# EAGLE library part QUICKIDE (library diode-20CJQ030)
Quick Logic's QuickIDE Intel XScale PXA2xx to IDE Bridge Description: The QuickIDE device is a full featured IDE Controller companion device for the Intel XScale PXA2xxx line of embedded processors. This device offers extremely high throughput while consuming very little power. With its on-board Sector Buffer RAM, the device allows the XScale CPU to perform read and write operations in full 512- byte sectors without interruption or waiting for the externally connected IDE device to be 'ready'. This device connects to the XScale CPU via its static memory interface. Variable Latency Input and Output (VLIO) is handled automatically by the QuickIDE device through use of the RDY signal. The RDY signal is only used to properly synchronize the QuickIDE device's responses to the XScale read and write commands during high-speed bus operation the QuickIDE device does not assert the RDY signal while it is waiting for responses from the externally connected IDE device. Instead, after an IDE command is given to the QuickIDE device, an interrupt is asserted to the XScale CPU to indicate that the externally connected device has responded and that the internal sector buffer is ready for read or write. Although the IDE interface is 16-bits wide, the QuickIDE device 'stacks' the IDE data words properly in the internal sector buffers so that the XScale device can perform all read and write operations in 32-bit mode. The QuickIDE device is based upon QuickLogic's proven programmable logic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
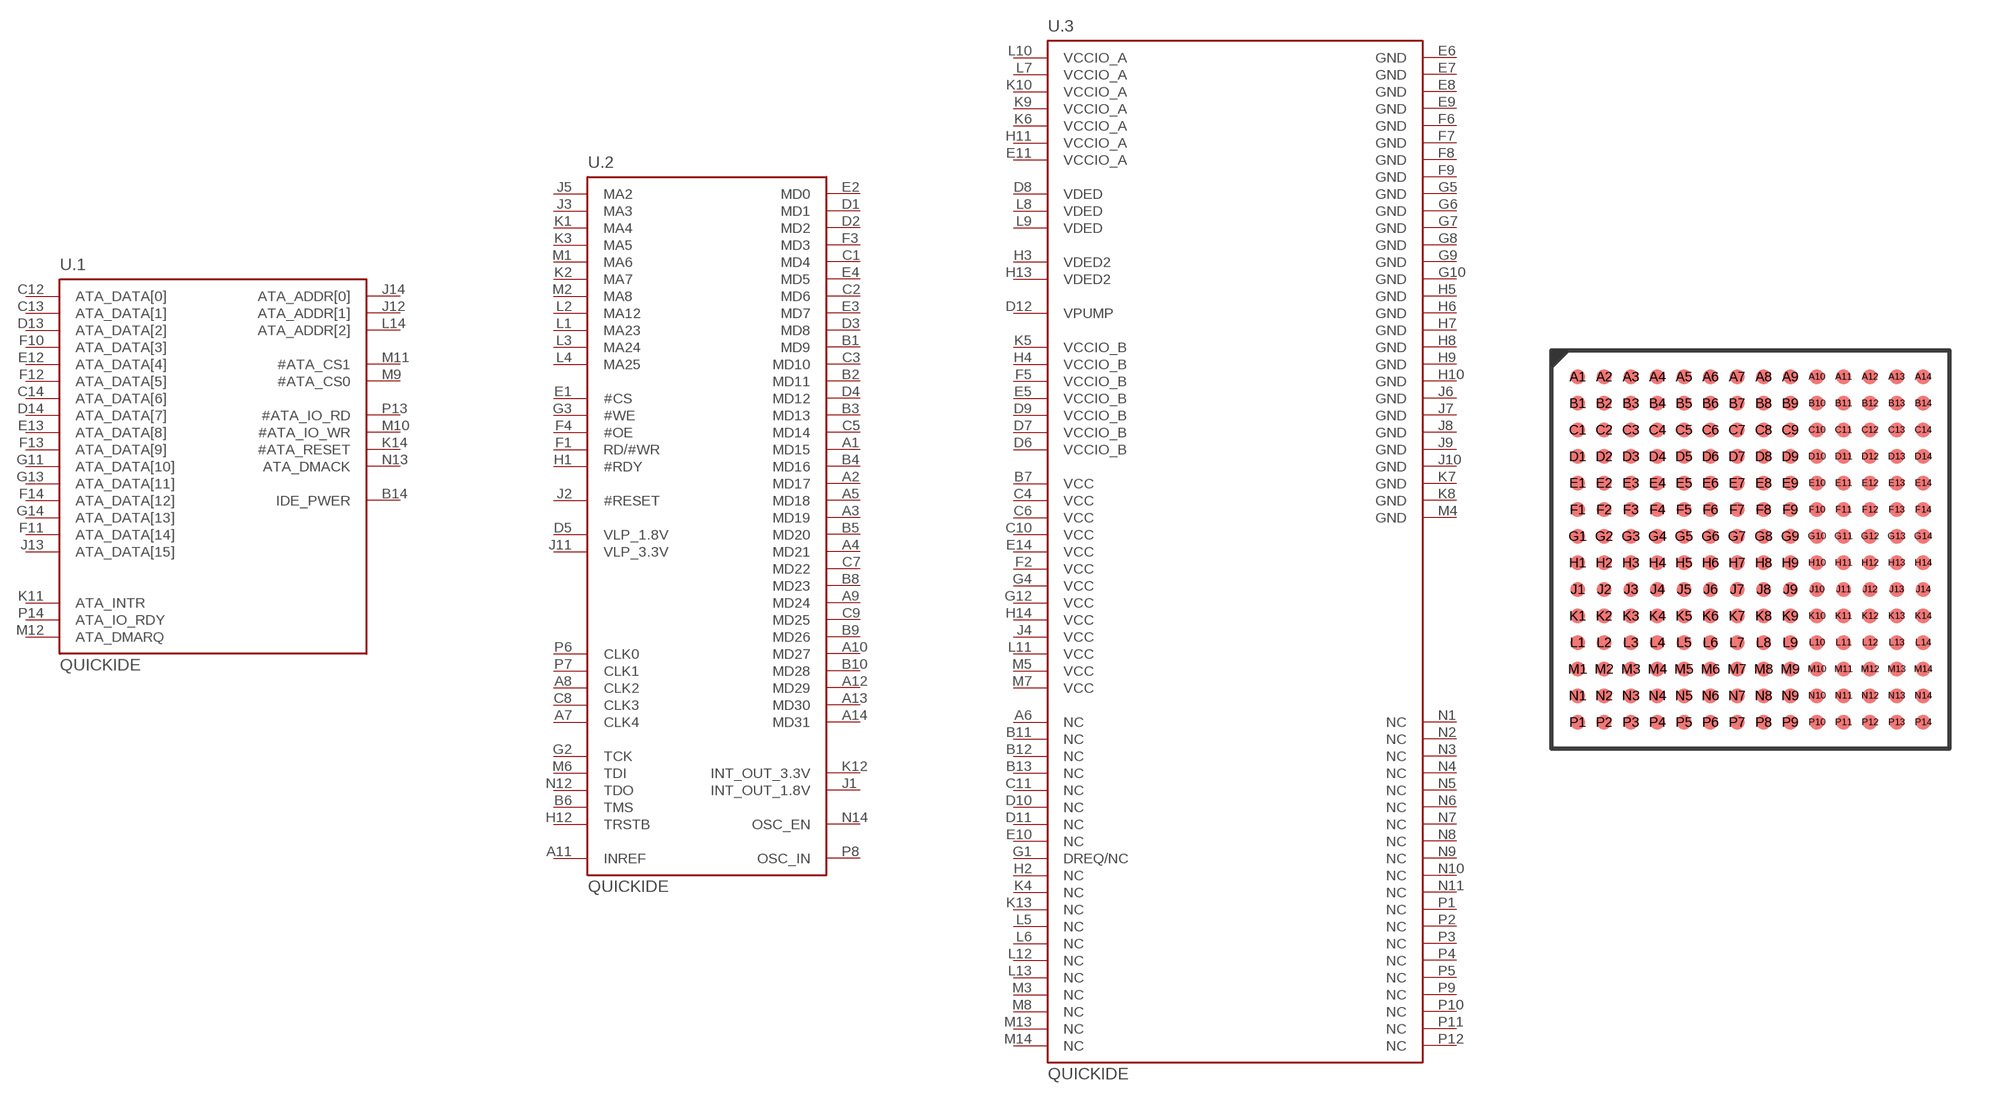
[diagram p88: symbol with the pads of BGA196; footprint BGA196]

Designator prefix U; gates .3=QUICKIDE_PWR .1=QUICKIDE_ATA .2=QUICKIDE_VLIO

## QUICKIDE-V3  [BGA196]
A1  .2:MD15
A2  .2:MD17
A3  .2:MD19
A4  .2:MD21
A5  .2:MD18
A6  .3:NC  nc
A7  .2:CLK4  in
A8  .2:CLK2  in
A9  .2:MD24
A10  .2:MD27
A11  .2:INREF  in
A12  .2:MD29
A13  .2:MD30
A14  .2:MD31
B1  .2:MD9
B2  .2:MD11
B3  .2:MD13
B4  .2:MD16
B5  .2:MD20
B6  .2:TMS  in
B7  .3:VCC  pwr
B8  .2:MD23
B9  .2:MD26
B10  .2:MD28
B11  .3:NC  nc
B12  .3:NC  nc
B13  .3:NC  nc
B14  .1:IDE_PWER  out
C1  .2:MD4
C2  .2:MD6
C3  .2:MD10
C4  .3:VCC  pwr
C5  .2:MD14
C6  .3:VCC  pwr
C7  .2:MD22
C8  .2:CLK3  in
C9  .2:MD25
C10  .3:VCC  pwr
C11  .3:NC  nc
C12  .1:ATA_DATA[0]
C13  .1:ATA_DATA[1]
C14  .1:ATA_DATA[6]
D1  .2:MD1
D2  .2:MD2
D3  .2:MD8
D4  .2:MD12
D5  .2:VLP_1.8V  in
D6  .3:VCCIO_B  pwr
D7  .3:VCCIO_B  pwr
D8  .3:VDED  pwr
D9  .3:VCCIO_B  pwr
D10  .3:NC  nc
D11  .3:NC  nc
D12  .3:VPUMP  pwr
D13  .1:ATA_DATA[2]
D14  .1:ATA_DATA[7]
E1  .2:#CS  in
E2  .2:MD0
E3  .2:MD7
E4  .2:MD5
E5  .3:VCCIO_B  pwr
E6  .3:GND  pwr
E7  .3:GND  pwr
E8  .3:GND  pwr
E9  .3:GND  pwr
E10  .3:NC  nc
E11  .3:VCCIO_A  pwr
E12  .1:ATA_DATA[4]
E13  .1:ATA_DATA[8]
E14  .3:VCC  pwr
F1  .2:RD/#WR  in
F2  .3:VCC  pwr
F3  .2:MD3
F4  .2:#OE  in
F5  .3:VCCIO_B  pwr
F6  .3:GND  pwr
F7  .3:GND  pwr
F8  .3:GND  pwr
F9  .3:GND  pwr
F10  .1:ATA_DATA[3]
F11  .1:ATA_DATA[14]
F12  .1:ATA_DATA[5]
F13  .1:ATA_DATA[9]
F14  .1:ATA_DATA[12]
G1  .3:DREQ/NC  out
G2  .2:TCK  in
G3  .2:#WE  in
G4  .3:VCC  pwr
G5  .3:GND  pwr
G6  .3:GND  pwr
G7  .3:GND  pwr
G8  .3:GND  pwr
G9  .3:GND  pwr
G10  .3:GND  pwr
G11  .1:ATA_DATA[10]
G12  .3:VCC  pwr
G13  .1:ATA_DATA[11]
G14  .1:ATA_DATA[13]
H1  .2:#RDY  out
H2  .3:NC  nc
H3  .3:VDED2  pwr
H4  .3:VCCIO_B  pwr
H5  .3:GND  pwr
H6  .3:GND  pwr
H7  .3:GND  pwr
H8  .3:GND  pwr
H9  .3:GND  pwr
H10  .3:GND  pwr
H11  .3:VCCIO_A  pwr
H12  .2:TRSTB  in
H13  .3:VDED2  pwr
H14  .3:VCC  pwr
J1  .2:INT_OUT_1.8V  out
J2  .2:#RESET  in
J3  .2:MA3  in
J4  .3:VCC  pwr
J5  .2:MA2  in
J6  .3:GND  pwr
J7  .3:GND  pwr
J8  .3:GND  pwr
J9  .3:GND  pwr
J10  .3:GND  pwr
J11  .2:VLP_3.3V
J12  .1:ATA_ADDR[1]  out
J13  .1:ATA_DATA[15]
J14  .1:ATA_ADDR[0]  out
K1  .2:MA4  in
K2  .2:MA7  in
K3  .2:MA5  in
K4  .3:NC  nc
K5  .3:VCCIO_B  pwr
K6  .3:VCCIO_A  pwr
K7  .3:GND  pwr
K8  .3:GND  pwr
K9  .3:VCCIO_A  pwr
K10  .3:VCCIO_A  pwr
K11  .1:ATA_INTR  in
K12  .2:INT_OUT_3.3V  out
K13  .3:NC  nc
K14  .1:#ATA_RESET  out
L1  .2:MA23  in
L2  .2:MA12  in
L3  .2:MA24  in
L4  .2:MA25  in
L5  .3:NC  nc
L6  .3:NC  nc
L7  .3:VCCIO_A  pwr
L8  .3:VDED  pwr
L9  .3:VDED  pwr
L10  .3:VCCIO_A  pwr
L11  .3:VCC  pwr
L12  .3:NC  nc
L13  .3:NC  nc
L14  .1:ATA_ADDR[2]  out
M1  .2:MA6  in
M2  .2:MA8  in
M3  .3:NC  nc
M4  .3:GND  pwr
M5  .3:VCC  pwr
M6  .2:TDI  in
M7  .3:VCC  pwr
M8  .3:NC  nc
M9  .1:#ATA_CS0  out
M10  .1:#ATA_IO_WR  out
M11  .1:#ATA_CS1  out
M12  .1:ATA_DMARQ  in
M13  .3:NC  nc
M14  .3:NC  nc
N1  .3:NC  nc
N2  .3:NC  nc
N3  .3:NC  nc
N4  .3:NC  nc
N5  .3:NC  nc
N6  .3:NC  nc
N7  .3:NC  nc
N8  .3:NC  nc
N9  .3:NC  nc
N10  .3:NC  nc
N11  .3:NC  nc
N12  .2:TDO  out
N13  .1:ATA_DMACK  out
N14  .2:OSC_EN  out
P1  .3:NC  nc
P2  .3:NC  nc
P3  .3:NC  nc
P4  .3:NC  nc
P5  .3:NC  nc
P6  .2:CLK0  in
P7  .2:CLK1  in
P8  .2:OSC_IN  in
P9  .3:NC  nc
P10  .3:NC  nc
P11  .3:NC  nc
P12  .3:NC  nc
P13  .1:#ATA_IO_RD  out
P14  .1:ATA_IO_RDY  in

## Footprint BGA196 (pad centres in mm)
Ball Grid Array 196 used for the QucikIDE from QuickLogic
smd 0.45 x 0.45: A1 -5.2,5.2; A2 -4.4,5.2; A3 -3.6,5.2; A4 -2.8,5.2; A5 -2,5.2; A6 -1.2,5.2; A7 -0.4,5.2; A8 0.4,5.2; A9 1.2,5.2; A10 2,5.2; A11 2.8,5.2; A12 3.6,5.2; A13 4.4,5.2; A14 5.2,5.2; B1 -5.2,4.4; B2 -4.4,4.4; B3 -3.6,4.4; B4 -2.8,4.4; B5 -2,4.4; B6 -1.2,4.4; B7 -0.4,4.4; B8 0.4,4.4; B9 1.2,4.4; B10 2,4.4; B11 2.8,4.4; B12 3.6,4.4; B13 4.4,4.4; B14 5.2,4.4; C1 -5.2,3.6; C2 -4.4,3.6; C3 -3.6,3.6; C4 -2.8,3.6; C5 -2,3.6; C6 -1.2,3.6; C7 -0.4,3.6; C8 0.4,3.6; C9 1.2,3.6; C10 2,3.6; C11 2.8,3.6; C12 3.6,3.6; C13 4.4,3.6; C14 5.2,3.6; D1 -5.2,2.8; D2 -4.4,2.8; D3 -3.6,2.8; D4 -2.8,2.8; D5 -2,2.8; D6 -1.2,2.8; D7 -0.4,2.8; D8 0.4,2.8; D9 1.2,2.8; D10 2,2.8; D11 2.8,2.8; D12 3.6,2.8; D13 4.4,2.8; D14 5.2,2.8; E1 -5.2,2; E2 -4.4,2; E3 -3.6,2; E4 -2.8,2; E5 -2,2; E6 -1.2,2; E7 -0.4,2; E8 0.4,2; E9 1.2,2; E10 2,2; E11 2.8,2; E12 3.6,2; E13 4.4,2; E14 5.2,2; F1 -5.2,1.2; F2 -4.4,1.2; F3 -3.6,1.2; F4 -2.8,1.2; F5 -2,1.2; F6 -1.2,1.2; F7 -0.4,1.2; F8 0.4,1.2; F9 1.2,1.2; F10 2,1.2; F11 2.8,1.2; F12 3.6,1.2; F13 4.4,1.2; F14 5.2,1.2; G1 -5.2,0.4; G2 -4.4,0.4; G3 -3.6,0.4; G4 -2.8,0.4; G5 -2,0.4; G6 -1.2,0.4; G7 -0.4,0.4; G8 0.4,0.4; G9 1.2,0.4; G10 2,0.4; G11 2.8,0.4; G12 3.6,0.4; G13 4.4,0.4; G14 5.2,0.4; H1 -5.2,-0.4; H2 -4.4,-0.4; H3 -3.6,-0.4; H4 -2.8,-0.4; H5 -2,-0.4; H6 -1.2,-0.4; H7 -0.4,-0.4; H8 0.4,-0.4; H9 1.2,-0.4; H10 2,-0.4; H11 2.8,-0.4; H12 3.6,-0.4; H13 4.4,-0.4; H14 5.2,-0.4; J1 -5.2,-1.2; J2 -4.4,-1.2; J3 -3.6,-1.2; J4 -2.8,-1.2; J5 -2,-1.2; J6 -1.2,-1.2; J7 -0.4,-1.2; J8 0.4,-1.2; J9 1.2,-1.2; J10 2,-1.2; J11 2.8,-1.2; J12 3.6,-1.2; J13 4.4,-1.2; J14 5.2,-1.2; K1 -5.2,-2; K2 -4.4,-2; K3 -3.6,-2; K4 -2.8,-2; K5 -2,-2; K6 -1.2,-2; K7 -0.4,-2; K8 0.4,-2; K9 1.2,-2; K10 2,-2; K11 2.8,-2; K12 3.6,-2; K13 4.4,-2; K14 5.2,-2; L1 -5.2,-2.8; L2 -4.4,-2.8; L3 -3.6,-2.8; L4 -2.8,-2.8; L5 -2,-2.8; L6 -1.2,-2.8; L7 -0.4,-2.8; L8 0.4,-2.8; L9 1.2,-2.8; L10 2,-2.8; L11 2.8,-2.8; L12 3.6,-2.8; L13 4.4,-2.8; L14 5.2,-2.8; M1 -5.2,-3.6; M2 -4.4,-3.6; M3 -3.6,-3.6; M4 -2.8,-3.6; M5 -2,-3.6; M6 -1.2,-3.6; M7 -0.4,-3.6; M8 0.4,-3.6; M9 1.2,-3.6; M10 2,-3.6; M11 2.8,-3.6; M12 3.6,-3.6; M13 4.4,-3.6; M14 5.2,-3.6; N1 -5.2,-4.4; N2 -4.4,-4.4; N3 -3.6,-4.4; N4 -2.8,-4.4; N5 -2,-4.4; N6 -1.2,-4.4; N7 -0.4,-4.4; N8 0.4,-4.4; N9 1.2,-4.4; N10 2,-4.4; N11 2.8,-4.4; N12 3.6,-4.4; N13 4.4,-4.4; N14 5.2,-4.4; P1 -5.2,-5.2; P2 -4.4,-5.2; P3 -3.6,-5.2; P4 -2.8,-5.2; P5 -2,-5.2; P6 -1.2,-5.2; P7 -0.4,-5.2; P8 0.4,-5.2; P9 1.2,-5.2; P10 2,-5.2; P11 2.8,-5.2; P12 3.6,-5.2; P13 4.4,-5.2; P14 5.2,-5.2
